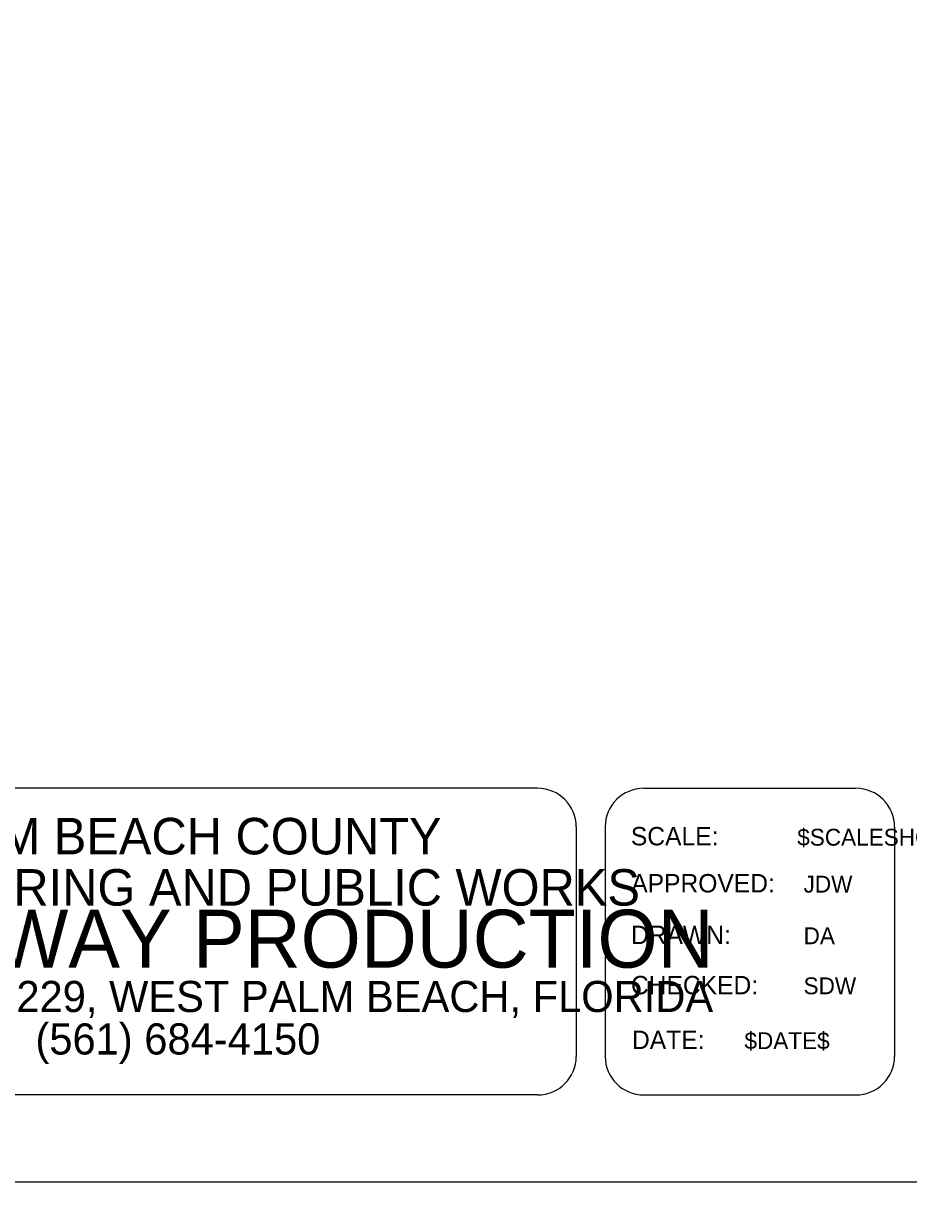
# Model space of a CAD drawing. Extents: x -0.7 to 16, y -0.9 to 9.7.
# Drawn here: x 9.999 to 12.024, y -0.9 to 1.75 of the extents above; entities that cross this region are included whole.
import ezdxf

# ---------------------------------------------------------------- set-up
doc = ezdxf.new("R2010")
doc.units = 0
for name, color, linetype in [('Default', 7, 'Continuous'), ('PlotBorder_dp', 7, 'Continuous'), ('TextMisc', 7, 'Continuous')]:
    doc.layers.add(name, color=color, linetype=linetype)

msp = doc.modelspace()

# ---------------------------------------------------------------- linework, layer by layer
at = {"layer": 'Default'}
for p, q in [((11.1756, 0), (8.7497, 0)), ((11.4182, 0), (11.9034, 0)), ((11.2638, -0.0882), (11.2638, -0.6131)), ((11.33, -0.0882), (11.33, -0.6131)), ((11.9916, -0.0882), (11.9916, -0.6131)), ((11.1756, -0.7014), (8.7497, -0.7014)), ((11.4182, -0.7014), (11.9034, -0.7014))]:
    msp.add_line(p, q, dxfattribs=at)
for centre, major_axis, start_param, end_param in [((11.1756, -0.0882), (0, 0.0882), 4.712389, 6.283185), ((11.4182, -0.0882), (0, 0.0882), 0, 1.570796), ((11.9034, -0.0882), (0, 0.0882), 4.712389, 6.283185), ((11.1756, -0.6131), (0, 0.0882), 3.141593, 4.712389), ((11.4182, -0.6131), (0, -0.0882), 4.712389, 6.283185), ((11.9034, -0.6131), (0, -0.0882), 0, 1.570796)]:
    msp.add_ellipse(centre, major_axis=major_axis, ratio=0.999927, start_param=start_param, end_param=end_param, dxfattribs=at)
at = {"layer": 'PlotBorder_dp'}
msp.add_lwpolyline([(-0.55, -0.9), (15.95, -0.9), (15.95, 9.7), (-0.55, 9.7)], close=True, dxfattribs=at)

# ---------------------------------------------------------------- texts
at = {"layer": 'Default'}
for s, height, p in [('PALM BEACH COUNTY', 0.083446, (9.7345, -0.1511)), ('ENGINEERING AND PUBLIC WORKS', 0.083468, (9.4745, -0.2683)), ('ROADWAY PRODUCTION', 0.132369, (9.4241, -0.4101)), ('P.O. BOX 21229, WEST PALM BEACH, FLORIDA', 0.071224, (9.4333, -0.5117)), ('(561) 684-4150', 0.071224, (10.0274, -0.6088))]:
    msp.add_text(s, height=height, rotation=360, dxfattribs=at).set_placement(p)
for s, height, p in [('SCALE:', 0.04207, (11.3888, -0.1305)), ('APPROVED:', 0.04207, (11.3896, -0.2381)), ('JDW', 0.03855, (11.7836, -0.2384)), ('DRAWN:', 0.04207, (11.389, -0.3563)), ('DA ', 0.03855, (11.7836, -0.3565)), ('CHECKED:', 0.04207, (11.3889, -0.4711)), ('SDW', 0.03855, (11.7836, -0.471)), ('DATE:', 0.04207, (11.3913, -0.5963)), ('$DATE$', 0.03855, (11.6484, -0.5965))]:
    msp.add_text(s, height=height, dxfattribs=at).set_placement(p)
at = {"layer": 'TextMisc'}
msp.add_text('$SCALESHORT$', height=0.038546, dxfattribs=at).set_placement((11.7691, -0.1311))

doc.saveas('drawing.dxf')
